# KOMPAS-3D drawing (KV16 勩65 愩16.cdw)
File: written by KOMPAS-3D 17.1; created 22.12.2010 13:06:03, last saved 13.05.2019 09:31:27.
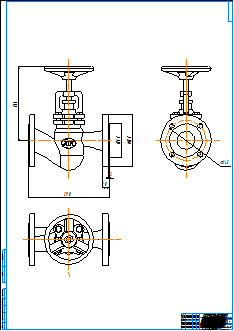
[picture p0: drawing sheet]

Title block, sheet 1: name: KV16 Ду65 Ру16; material: Внимание! Данный продукт является объектом авторского права ООО «Торговый Дом АДЛ». / Запрещается изменение, копирование, распространение / (в том числе путем копирования на другие сайты и ресурсы в Интернете) / или любое иное использование информации и объектов без предварительного / согласия правообладателя (ООО «Торговый Дом АДЛ»).; scale: 1:1; sheets: 1; organisation: ООО "Торговый дом АДЛ"; sheet format: A0; stored path: \\adlc.lan\data\АДЛ_ПКД\3D-модели\ADL production\Вентили ГРАНВЕНТ\KV16\KOMPAS 2D\KV16 Ду65 Ру16.cdw

Views: Спереди 1, Проекционный вид 2, Проекционный вид 3
Dimensions and other numbers on the sheet: 120; 185; 2; 20; 290; 145; 266; 1:1; 1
